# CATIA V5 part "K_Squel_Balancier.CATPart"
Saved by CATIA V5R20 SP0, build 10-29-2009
Part number: Squelette_balancier
Publications: "Point.5", "Plan.13", "Plan.12", "Plan.1", "Plan.10", "Point.1", "Point.4", "Sommet", "Droite.7", "Plan.14", "Plan.11"
Bounding box of the stored display mesh (mm): x -38 to 0, y 106.066 to 196.271, z -194.454 to -106.066
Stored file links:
  G:\Khaled_CFAO_2011\ST2M\ST2M_GR2\plakomicki\Khaled\CAD_ThinkMOTION\K_Squel_Balancier.CATPart
  G:\Khaled_CFAO_2011\ST2M\ST2M_GR2\plakomicki\Khaled\CAD_ThinkMOTION\K_Squelette.CATProduct
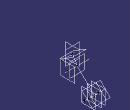
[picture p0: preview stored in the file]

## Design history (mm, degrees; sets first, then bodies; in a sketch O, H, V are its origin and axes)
External parameters (linked from other documents)
  External.entraxe_struct_balancier = 38 mm
Set1
  Plane1: linked copy from another document
  Point1: linked copy from another document
  Point2: linked copy from another document
  Plane2: linked copy from another document
Set2
  Plane3 "Plan_entraxe_balancier_struct": type Offset, RefPlane Plane1, Offset -38 {= -External.entraxe_struct_balancier}
  Point3: type OnPlane, Support Plane3, RefPoint Point1, H 0, V 0, Direction (0, 1, 0)
  Line1: type PtPt, FirstPoint Point1, SecondPoint Point3
  Plane4: type OffsetPt, RefPlane zx-plane, RefPoint Point3
  Plane5: type Angle, RefPlane Plane4, Direction Line1, Angle 60
  Line2: type PtPt, FirstPoint Point3, SecondPoint Point2
  Line3: type PtDir, RefPoint Point2, Direction Plane2, Start 0, End 33
  Plane6: type OffsetPt, RefPlane yz-plane, RefPoint vertex of Line3
  Plane7: type OffsetPt, RefPlane zx-plane, RefPoint Point2
  Plane8: type Angle, RefPlane Plane7, Direction Line3, Angle -45
  Plane9: type Offset, RefPlane Plane8, Offset 85
  Point4: type OnPlane, Support Plane9, RefPoint Point2, H 0, V 0, Direction (-1, 0, 0)
  Line4: type PtPt, FirstPoint Point4, SecondPoint Point2
  Plane10: type OffsetPt, RefPlane yz-plane, RefPoint Point4
  Line5: type PtDir, RefPoint Point4, Direction Plane10, Start 0, End 33
  Plane11: type Angle, RefPlane Plane9, Direction Line5, Angle 90
  Plane12: type Offset, RefPlane Plane11, Offset 20
  Point5: type OnPlane, Support Plane12, RefPoint Point4, H 0, V 0, Direction (-1, 0, 0)
  Line6: type PtPt, FirstPoint Point5, SecondPoint Point4
  Plane13: type OffsetPt, RefPlane yz-plane, RefPoint Point5
  Line7: type PtDir, RefPoint Point5, Direction Plane13, Start 0, End 33
  Plane14: type OffsetPt, RefPlane yz-plane, RefPoint vertex of Line7
Body1 (main body)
